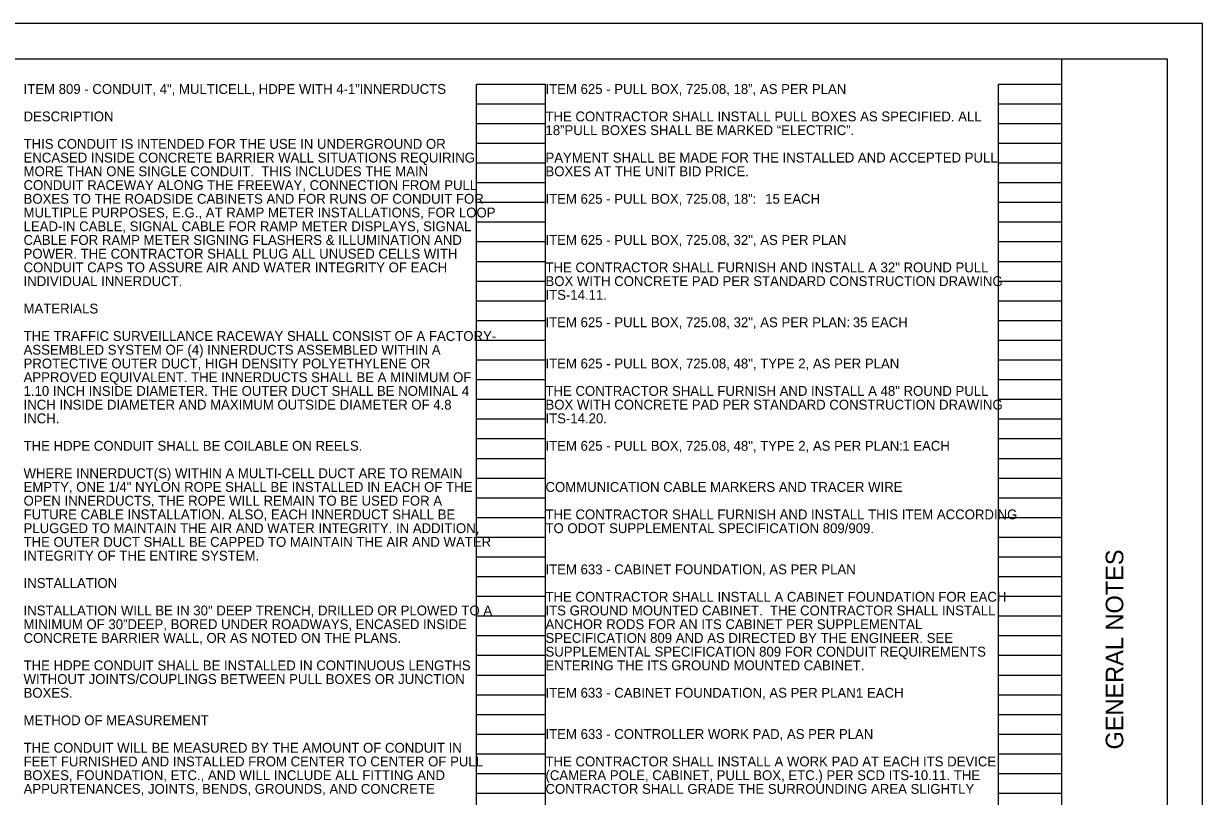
# Model space of a CAD drawing. Extents: x 0 to 34, y 0 to 22.
# Drawn here: x 17.24 to 34, y 11.01 to 22 of the extents above; entities that cross this region are included whole.
import ezdxf

# ---------------------------------------------------------------- set-up
doc = ezdxf.new("R2010")
doc.units = 0
for name, color, linetype in [('SH_Border', 7, 'Continuous'), ('SH_Cut_Line', 7, 'Continuous'), ('SH_Data', 7, 'Continuous'), ('SH_Text', 7, 'Continuous')]:
    doc.layers.add(name, color=color, linetype=linetype)

msp = doc.modelspace()

# ---------------------------------------------------------------- linework, layer by layer
at = {"layer": 'SH_Border'}
msp.add_line((32, 0.5), (32, 21.5), dxfattribs=at)
msp.add_lwpolyline([(1.5, 21.5), (33.5, 21.5), (33.5, 0.5), (1.5, 0.5)], close=True, dxfattribs=at)
at = {"layer": 'SH_Cut_Line'}
msp.add_lwpolyline([(0, 0), (34, 0), (34, 22), (0, 22)], close=True, dxfattribs=at)
at = {"layer": 'SH_Data'}
for p, q in [((23.68, 0.98), (23.68, 21.14)), ((23.68, 21.14), (24.66, 21.14)), ((24.66, 0.98), (24.66, 21.14)), ((31.1, 0.98), (31.1, 21.14)), ((31.1, 21.14), (32, 21.14)), ((32, 0.98), (32, 21.14)), ((23.68, 20.86), (24.66, 20.86)), ((31.1, 20.86), (32, 20.86)), ((23.68, 20.58), (24.66, 20.58)), ((31.1, 20.58), (32, 20.58)), ((23.68, 20.3), (24.66, 20.3)), ((31.1, 20.3), (32, 20.3)), ((23.68, 20.02), (24.66, 20.02)), ((31.1, 20.02), (32, 20.02)), ((23.68, 19.74), (24.66, 19.74)), ((31.1, 19.74), (32, 19.74)), ((23.68, 19.46), (24.66, 19.46)), ((31.1, 19.46), (32, 19.46)), ((23.68, 19.18), (24.66, 19.18)), ((31.1, 19.18), (32, 19.18)), ((23.68, 18.9), (24.66, 18.9)), ((31.1, 18.9), (32, 18.9)), ((23.68, 18.62), (24.66, 18.62)), ((31.1, 18.62), (32, 18.62)), ((23.68, 18.34), (24.66, 18.34)), ((31.1, 18.34), (32, 18.34)), ((23.68, 18.06), (24.66, 18.06)), ((31.1, 18.06), (32, 18.06)), ((23.68, 17.78), (24.66, 17.78)), ((31.1, 17.78), (32, 17.78)), ((23.68, 17.5), (24.66, 17.5)), ((31.1, 17.5), (32, 17.5)), ((23.68, 17.22), (24.66, 17.22)), ((31.1, 17.22), (32, 17.22)), ((23.68, 16.94), (24.66, 16.94)), ((31.1, 16.94), (32, 16.94)), ((23.68, 16.66), (24.66, 16.66)), ((31.1, 16.66), (32, 16.66)), ((23.68, 16.38), (24.66, 16.38)), ((31.1, 16.38), (32, 16.38)), ((23.68, 16.1), (24.66, 16.1)), ((31.1, 16.1), (32, 16.1)), ((23.68, 15.82), (24.66, 15.82)), ((31.1, 15.82), (32, 15.82)), ((23.68, 15.54), (24.66, 15.54)), ((31.1, 15.54), (32, 15.54)), ((23.68, 15.26), (24.66, 15.26)), ((31.1, 15.26), (32, 15.26)), ((23.68, 14.98), (24.66, 14.98)), ((31.1, 14.98), (32, 14.98)), ((23.68, 14.7), (24.66, 14.7)), ((31.1, 14.7), (32, 14.7)), ((23.68, 14.42), (24.66, 14.42)), ((31.1, 14.42), (32, 14.42)), ((23.68, 14.14), (24.66, 14.14)), ((31.1, 14.14), (32, 14.14)), ((23.68, 13.86), (24.66, 13.86)), ((31.1, 13.86), (32, 13.86)), ((23.68, 13.58), (24.66, 13.58)), ((31.1, 13.58), (32, 13.58)), ((23.68, 13.3), (24.66, 13.3)), ((31.1, 13.3), (32, 13.3)), ((23.68, 13.02), (24.66, 13.02)), ((31.1, 13.02), (32, 13.02)), ((23.68, 12.74), (24.66, 12.74)), ((31.1, 12.74), (32, 12.74)), ((23.68, 12.46), (24.66, 12.46)), ((31.1, 12.46), (32, 12.46)), ((23.68, 12.18), (24.66, 12.18)), ((31.1, 12.18), (32, 12.18)), ((23.68, 11.9), (24.66, 11.9)), ((31.1, 11.9), (32, 11.9)), ((23.68, 11.62), (24.66, 11.62)), ((31.1, 11.62), (32, 11.62)), ((23.68, 11.34), (24.66, 11.34)), ((31.1, 11.34), (32, 11.34)), ((23.68, 11.06), (24.66, 11.06)), ((31.1, 11.06), (32, 11.06))]:
    msp.add_line(p, q, dxfattribs=at)

# ---------------------------------------------------------------- texts
msp.add_text('GENERAL NOTES', height=0.25, rotation=90, dxfattribs=at).set_placement((32.875, 11.682))
at = {"layer": 'SH_Text'}
for s, p in [('ITEM 809 - CONDUIT, 4", MULTICELL, HDPE WITH 4-1”INNERDUCTS', (17.24, 21)), ('ITEM 625 - PULL BOX, 725.08, 18”, AS PER PLAN', (24.66, 21)), ('DESCRIPTION ', (17.24, 20.61)), ('THE CONTRACTOR SHALL INSTALL PULL BOXES AS SPECIFIED. ALL ', (24.66, 20.61)), ('18”PULL BOXES SHALL BE MARKED “ELECTRIC”.', (24.66, 20.415)), ('THIS CONDUIT IS INTENDED FOR THE USE IN UNDERGROUND OR ', (17.24, 20.22)), ('ENCASED INSIDE CONCRETE BARRIER WALL SITUATIONS REQUIRING ', (17.24, 20.025)), ('PAYMENT SHALL BE MADE FOR THE INSTALLED AND ACCEPTED PULL ', (24.66, 20.025)), ('MORE THAN ONE SINGLE CONDUIT.  THIS INCLUDES THE MAIN ', (17.24, 19.83)), ('BOXES AT THE UNIT BID PRICE.', (24.66, 19.83)), ('CONDUIT RACEWAY ALONG THE FREEWAY, CONNECTION FROM PULL ', (17.24, 19.634)), ('BOXES TO THE ROADSIDE CABINETS AND FOR RUNS OF CONDUIT FOR ', (17.24, 19.439)), ('ITEM 625 - PULL BOX, 725.08, 18”: ', (24.66, 19.439)), ('15 EACH', (27.784, 19.439)), ('MULTIPLE PURPOSES, E.G., AT RAMP METER INSTALLATIONS, FOR LOOP ', (17.24, 19.244)), ('LEAD-IN CABLE, SIGNAL CABLE FOR RAMP METER DISPLAYS, SIGNAL ', (17.24, 19.049)), ('CABLE FOR RAMP METER SIGNING FLASHERS & ILLUMINATION AND ', (17.24, 18.854)), ('ITEM 625 - PULL BOX, 725.08, 32", AS PER PLAN', (24.66, 18.854)), ('POWER. THE CONTRACTOR SHALL PLUG ALL UNUSED CELLS WITH ', (17.24, 18.659)), ('CONDUIT CAPS TO ASSURE AIR AND WATER INTEGRITY OF EACH ', (17.24, 18.464)), ('THE CONTRACTOR SHALL FURNISH AND INSTALL A 32" ROUND PULL ', (24.66, 18.464)), ('INDIVIDUAL INNERDUCT.', (17.24, 18.269)), ('BOX WITH CONCRETE PAD PER STANDARD CONSTRUCTION DRAWING ', (24.66, 18.269)), ('ITS-14.11.', (24.66, 18.074)), ('MATERIALS ', (17.24, 17.879)), ('ITEM 625 - PULL BOX, 725.08, 32", AS PER PLAN: ', (24.66, 17.684)), ('35 EACH', (29.03, 17.684)), ('THE TRAFFIC SURVEILLANCE RACEWAY SHALL CONSIST OF A FACTORY-', (17.24, 17.489)), ('ASSEMBLED SYSTEM OF (4) INNERDUCTS ASSEMBLED WITHIN A ', (17.24, 17.293)), ('PROTECTIVE OUTER DUCT, HIGH DENSITY POLYETHYLENE OR ', (17.24, 17.098)), ('ITEM 625 - PULL BOX, 725.08, 48", TYPE 2, AS PER PLAN', (24.66, 17.098)), ('APPROVED EQUIVALENT. THE INNERDUCTS SHALL BE A MINIMUM OF ', (17.24, 16.903)), ('1.10 INCH INSIDE DIAMETER. THE OUTER DUCT SHALL BE NOMINAL 4 ', (17.24, 16.708)), ('THE CONTRACTOR SHALL FURNISH AND INSTALL A 48" ROUND PULL ', (24.66, 16.708)), ('INCH INSIDE DIAMETER AND MAXIMUM OUTSIDE DIAMETER OF 4.8 ', (17.24, 16.513)), ('BOX WITH CONCRETE PAD PER STANDARD CONSTRUCTION DRAWING ', (24.66, 16.513)), ('INCH.', (17.24, 16.318)), ('ITS-14.20.', (24.66, 16.318)), ('THE HDPE CONDUIT SHALL BE COILABLE ON REELS.  ', (17.24, 15.928)), ('ITEM 625 - PULL BOX, 725.08, 48", TYPE 2, AS PER PLAN: ', (24.66, 15.928)), ('1 EACH', (29.733, 15.928)), ('WHERE INNERDUCT(S) WITHIN A MULTI-CELL DUCT ARE TO REMAIN ', (17.24, 15.538)), ('EMPTY, ONE 1/4" NYLON ROPE SHALL BE INSTALLED IN EACH OF THE ', (17.24, 15.343)), ('COMMUNICATION CABLE MARKERS AND TRACER WIRE', (24.66, 15.343)), ('OPEN INNERDUCTS, THE ROPE WILL REMAIN TO BE USED FOR A ', (17.24, 15.148)), ('FUTURE CABLE INSTALLATION. ALSO, EACH INNERDUCT SHALL BE ', (17.24, 14.953)), ('THE CONTRACTOR SHALL FURNISH AND INSTALL THIS ITEM ACCORDING ', (24.66, 14.953)), ('PLUGGED TO MAINTAIN THE AIR AND WATER INTEGRITY. IN ADDITION, ', (17.24, 14.757)), ('TO ODOT SUPPLEMENTAL SPECIFICATION 809/909.', (24.66, 14.757)), ('THE OUTER DUCT SHALL BE CAPPED TO MAINTAIN THE AIR AND WATER ', (17.24, 14.562)), ('INTEGRITY OF THE ENTIRE SYSTEM.', (17.24, 14.367)), ('ITEM 633 - CABINET FOUNDATION, AS PER PLAN', (24.66, 14.172)), ('INSTALLATION', (17.24, 13.977)), ('THE CONTRACTOR SHALL INSTALL A CABINET FOUNDATION FOR EACH ', (24.66, 13.782)), ('INSTALLATION WILL BE IN 30" DEEP TRENCH, DRILLED OR PLOWED TO A ', (17.24, 13.587)), ('ITS GROUND MOUNTED CABINET.  THE CONTRACTOR SHALL INSTALL ', (24.66, 13.587)), ('MINIMUM OF 30”DEEP, BORED UNDER ROADWAYS, ENCASED INSIDE ', (17.24, 13.392)), ('ANCHOR RODS FOR AN ITS CABINET PER SUPPLEMENTAL ', (24.66, 13.392)), ('CONCRETE BARRIER WALL, OR AS NOTED ON THE PLANS.', (17.24, 13.197)), ('SPECIFICATION 809 AND AS DIRECTED BY THE ENGINEER. SEE ', (24.66, 13.197)), ('SUPPLEMENTAL SPECIFICATION 809 FOR CONDUIT REQUIREMENTS ', (24.66, 13.002)), ('THE HDPE CONDUIT SHALL BE INSTALLED IN CONTINUOUS LENGTHS ', (17.24, 12.807)), ('ENTERING THE ITS GROUND MOUNTED CABINET.', (24.66, 12.807)), ('WITHOUT JOINTS/COUPLINGS BETWEEN PULL BOXES OR JUNCTION ', (17.24, 12.612)), ('BOXES.', (17.24, 12.417)), ('ITEM 633 - CABINET FOUNDATION, AS PER PLAN: ', (24.66, 12.417)), ('1 EACH', (29.075, 12.417)), ('METHOD OF MEASUREMENT', (17.24, 12.026)), ('ITEM 633 - CONTROLLER WORK PAD, AS PER PLAN', (24.66, 11.831)), ('THE CONDUIT WILL BE MEASURED BY THE AMOUNT OF CONDUIT IN ', (17.24, 11.636)), ('FEET FURNISHED AND INSTALLED FROM CENTER TO CENTER OF PULL ', (17.24, 11.441)), ('THE CONTRACTOR SHALL INSTALL A WORK PAD AT EACH ITS DEVICE ', (24.66, 11.441)), ('BOXES, FOUNDATION, ETC., AND WILL INCLUDE ALL FITTING AND ', (17.24, 11.246)), ('(CAMERA POLE, CABINET, PULL BOX, ETC.) PER SCD ITS-10.11. THE ', (24.66, 11.246)), ('APPURTENANCES, JOINTS, BENDS, GROUNDS, AND CONCRETE ', (17.24, 11.051)), ('CONTRACTOR SHALL GRADE THE SURROUNDING AREA SLIGHTLY ', (24.66, 11.051))]:
    msp.add_text(s, height=0.14, dxfattribs=at).set_placement(p)

doc.saveas('drawing.dxf')
